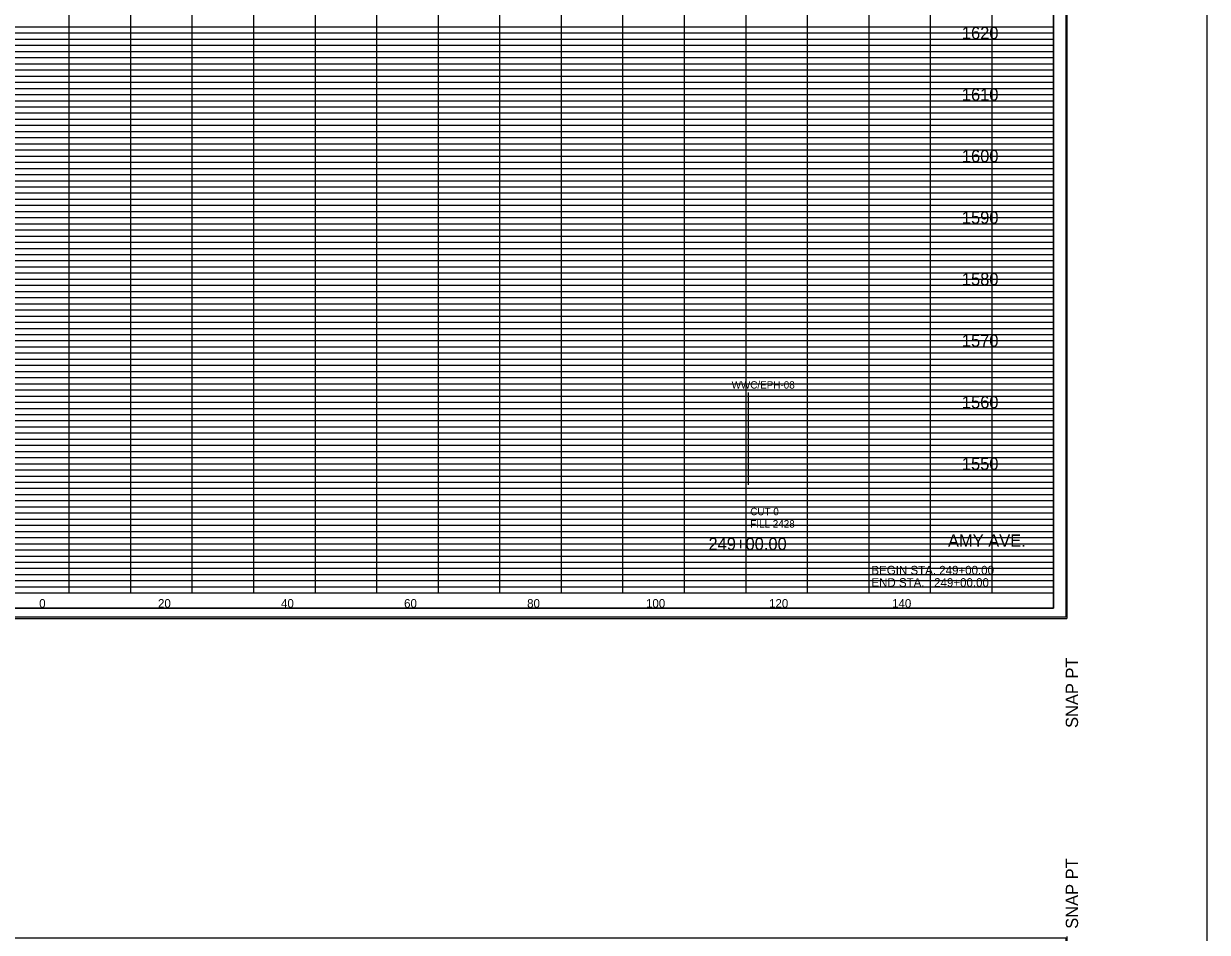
# Model space of a CAD drawing. Extents: x 955 to 1375, y 1248 to 3657.
# Drawn here: x 1152.6 to 1345, y 3104.8 to 3252.5 of the extents above; entities that cross this region are included whole.
import ezdxf

# ---------------------------------------------------------------- set-up
doc = ezdxf.new("R2010")
doc.units = 0
for name, color, linetype in [('DESIGN - SHEET - Corner Text', 7, 'Continuous'), ('DESIGN - SHEET - Light Grid', 7, 'Continuous'), ('DESIGN - SHEET - Linework', 7, 'Continuous'), ('DESIGN - SHEET - Plot Shape', 7, 'Continuous'), ('DESIGN - TYPICAL - Text', 7, 'Continuous'), ('DESIGN - UTILITIES - Cable (Overhead) with Text', 7, 'Continuous'), ('SURVEY - NON-TRANSPORTATION - Features', 7, 'Continuous'), ('SURVEY - NON-TRANSPORTATION - Features Text', 7, 'Continuous')]:
    doc.layers.add(name, color=color, linetype=linetype)

# ---------------------------------------------------------------- blocks, each defined once
blk = doc.blocks.new('XSTSHT')
at = {"layer": 'DESIGN - SHEET - Light Grid'}
for p, q in [((8, 9.2), (16, 9.2)), ((8, 9.1), (16, 9.1)), ((16, 9.2), (24, 9.2)), ((16, 9.1), (24, 9.1)), ((24, 9.2), (32, 9.2)), ((24, 9.1), (32, 9.1)), ((8, 8.9), (16, 8.9)), ((16, 8.9), (24, 8.9)), ((24, 8.9), (32, 8.9)), ((8, 8.8), (16, 8.8)), ((8, 8.7), (16, 8.7)), ((16, 8.8), (24, 8.8)), ((16, 8.7), (24, 8.7)), ((24, 8.8), (32, 8.8)), ((24, 8.7), (32, 8.7)), ((8, 8.6), (16, 8.6)), ((8, 8.5), (16, 8.5)), ((16, 8.6), (24, 8.6)), ((16, 8.5), (24, 8.5)), ((24, 8.6), (32, 8.6)), ((24, 8.5), (32, 8.5)), ((8, 8.4), (16, 8.4)), ((8, 8.3), (16, 8.3)), ((16, 8.4), (24, 8.4)), ((16, 8.3), (24, 8.3)), ((24, 8.4), (32, 8.4)), ((24, 8.3), (32, 8.3)), ((8, 8.2), (16, 8.2)), ((8, 8.1), (16, 8.1)), ((16, 8.2), (24, 8.2)), ((16, 8.1), (24, 8.1)), ((24, 8.2), (32, 8.2)), ((24, 8.1), (32, 8.1)), ((8, 7.9), (16, 7.9)), ((16, 7.9), (24, 7.9)), ((24, 7.9), (32, 7.9)), ((8, 7.8), (16, 7.8)), ((8, 7.7), (16, 7.7)), ((16, 7.8), (24, 7.8)), ((16, 7.7), (24, 7.7)), ((24, 7.8), (32, 7.8)), ((24, 7.7), (32, 7.7)), ((8, 7.6), (16, 7.6)), ((16, 7.6), (24, 7.6)), ((24, 7.6), (32, 7.6)), ((8, 7.5), (16, 7.5)), ((8, 7.4), (16, 7.4)), ((16, 7.5), (24, 7.5)), ((16, 7.4), (24, 7.4)), ((24, 7.5), (32, 7.5)), ((24, 7.4), (32, 7.4)), ((8, 7.3), (16, 7.3)), ((8, 7.2), (16, 7.2)), ((16, 7.3), (24, 7.3)), ((16, 7.2), (24, 7.2)), ((24, 7.3), (32, 7.3)), ((24, 7.2), (32, 7.2)), ((8, 7.1), (16, 7.1)), ((16, 7.1), (24, 7.1)), ((24, 7.1), (32, 7.1)), ((8, 6.9), (16, 6.9)), ((8, 6.8), (16, 6.8)), ((16, 6.9), (24, 6.9)), ((16, 6.8), (24, 6.8)), ((24, 6.9), (32, 6.9)), ((24, 6.8), (32, 6.8)), ((8, 6.7), (16, 6.7)), ((8, 6.6), (16, 6.6)), ((16, 6.7), (24, 6.7)), ((16, 6.6), (24, 6.6)), ((24, 6.7), (32, 6.7)), ((24, 6.6), (32, 6.6)), ((8, 6.5), (16, 6.5)), ((8, 6.4), (16, 6.4)), ((16, 6.5), (24, 6.5)), ((16, 6.4), (24, 6.4)), ((24, 6.5), (32, 6.5)), ((24, 6.4), (32, 6.4)), ((8, 6.3), (16, 6.3)), ((8, 6.2), (16, 6.2)), ((16, 6.3), (24, 6.3)), ((16, 6.2), (24, 6.2)), ((24, 6.3), (32, 6.3)), ((24, 6.2), (32, 6.2)), ((8, 6.1), (16, 6.1)), ((16, 6.1), (24, 6.1)), ((24, 6.1), (32, 6.1)), ((8, 5.9), (16, 5.9)), ((8, 5.8), (16, 5.8)), ((16, 5.9), (24, 5.9)), ((16, 5.8), (24, 5.8)), ((24, 5.9), (32, 5.9)), ((24, 5.8), (32, 5.8)), ((8, 5.7), (16, 5.7)), ((8, 5.6), (16, 5.6)), ((16, 5.7), (24, 5.7)), ((16, 5.6), (24, 5.6)), ((24, 5.7), (32, 5.7)), ((24, 5.6), (32, 5.6)), ((8, 5.5), (16, 5.5)), ((8, 5.4), (16, 5.4)), ((16, 5.5), (24, 5.5)), ((16, 5.4), (24, 5.4)), ((24, 5.5), (32, 5.5)), ((24, 5.4), (32, 5.4)), ((8, 5.3), (16, 5.3)), ((8, 5.2), (16, 5.2)), ((16, 5.3), (24, 5.3)), ((16, 5.2), (24, 5.2)), ((24, 5.3), (32, 5.3)), ((24, 5.2), (32, 5.2)), ((8, 5.1), (16, 5.1)), ((16, 5.1), (24, 5.1)), ((24, 5.1), (32, 5.1)), ((8, 4.9), (16, 4.9)), ((16, 4.9), (24, 4.9)), ((24, 4.9), (32, 4.9)), ((8, 4.8), (16, 4.8)), ((8, 4.7), (16, 4.7)), ((16, 4.8), (24, 4.8)), ((16, 4.7), (24, 4.7)), ((24, 4.8), (32, 4.8)), ((24, 4.7), (32, 4.7)), ((8, 4.6), (16, 4.6)), ((8, 4.5), (16, 4.5)), ((16, 4.6), (24, 4.6)), ((16, 4.5), (24, 4.5)), ((24, 4.6), (32, 4.6)), ((24, 4.5), (32, 4.5)), ((8, 4.4), (16, 4.4)), ((8, 4.3), (16, 4.3)), ((16, 4.4), (24, 4.4)), ((16, 4.3), (24, 4.3)), ((24, 4.4), (32, 4.4)), ((24, 4.3), (32, 4.3)), ((8, 4.2), (16, 4.2)), ((8, 4.1), (16, 4.1)), ((16, 4.2), (24, 4.2)), ((16, 4.1), (24, 4.1)), ((24, 4.2), (32, 4.2)), ((24, 4.1), (32, 4.1)), ((8, 3.9), (16, 3.9)), ((16, 3.9), (24, 3.9)), ((24, 3.9), (32, 3.9)), ((8, 3.8), (16, 3.8)), ((8, 3.7), (16, 3.7)), ((16, 3.8), (24, 3.8)), ((16, 3.7), (24, 3.7)), ((24, 3.8), (32, 3.8)), ((24, 3.7), (32, 3.7)), ((8, 3.6), (16, 3.6)), ((8, 3.5), (16, 3.5)), ((16, 3.6), (24, 3.6)), ((16, 3.5), (24, 3.5)), ((24, 3.6), (32, 3.6)), ((24, 3.5), (32, 3.5)), ((8, 3.4), (16, 3.4)), ((8, 3.3), (16, 3.3)), ((16, 3.4), (24, 3.4)), ((16, 3.3), (24, 3.3)), ((24, 3.4), (32, 3.4)), ((24, 3.3), (32, 3.3)), ((8, 3.2), (16, 3.2)), ((8, 3.1), (16, 3.1)), ((16, 3.2), (24, 3.2)), ((16, 3.1), (24, 3.1)), ((24, 3.2), (32, 3.2)), ((24, 3.1), (32, 3.1)), ((8, 2.9), (16, 2.9)), ((16, 2.9), (24, 2.9)), ((24, 2.9), (32, 2.9)), ((8, 2.8), (16, 2.8)), ((8, 2.7), (16, 2.7)), ((16, 2.8), (24, 2.8)), ((16, 2.7), (24, 2.7)), ((24, 2.8), (32, 2.8)), ((24, 2.7), (32, 2.7)), ((8, 2.6), (16, 2.6)), ((16, 2.6), (24, 2.6)), ((24, 2.6), (32, 2.6)), ((8, 2.5), (16, 2.5)), ((8, 2.4), (16, 2.4)), ((16, 2.5), (24, 2.5)), ((16, 2.4), (24, 2.4)), ((24, 2.5), (32, 2.5)), ((24, 2.4), (32, 2.4)), ((8, 2.3), (16, 2.3)), ((8, 2.2), (16, 2.2)), ((16, 2.3), (24, 2.3)), ((16, 2.2), (24, 2.2)), ((24, 2.3), (32, 2.3)), ((24, 2.2), (32, 2.2)), ((8, 2.1), (16, 2.1)), ((16, 2.1), (24, 2.1)), ((24, 2.1), (32, 2.1)), ((8, 1.9), (16, 1.9)), ((8, 1.8), (16, 1.8)), ((16, 1.9), (24, 1.9)), ((16, 1.8), (24, 1.8)), ((24, 1.9), (32, 1.9)), ((24, 1.8), (32, 1.8)), ((8, 1.7), (16, 1.7)), ((8, 1.6), (16, 1.6)), ((16, 1.7), (24, 1.7)), ((16, 1.6), (24, 1.6)), ((24, 1.7), (32, 1.7)), ((24, 1.6), (32, 1.6)), ((8, 1.5), (16, 1.5)), ((8, 1.4), (16, 1.4)), ((16, 1.5), (24, 1.5)), ((16, 1.4), (24, 1.4)), ((24, 1.5), (32, 1.5)), ((24, 1.4), (32, 1.4)), ((8, 1.3), (16, 1.3)), ((8, 1.2), (16, 1.2)), ((16, 1.3), (24, 1.3)), ((16, 1.2), (24, 1.2)), ((24, 1.3), (32, 1.3)), ((24, 1.2), (32, 1.2)), ((8, 1.1), (16, 1.1)), ((16, 1.1), (24, 1.1)), ((24, 1.1), (32, 1.1)), ((8, 0.9), (16, 0.9)), ((8, 0.8), (16, 0.8)), ((16, 0.9), (24, 0.9)), ((16, 0.8), (24, 0.8)), ((24, 0.9), (32, 0.9)), ((24, 0.8), (32, 0.8)), ((8, 0.7), (16, 0.7)), ((8, 0.6), (16, 0.6)), ((16, 0.7), (24, 0.7)), ((16, 0.6), (24, 0.6)), ((24, 0.7), (32, 0.7)), ((24, 0.6), (32, 0.6)), ((8, 0.5), (16, 0.5)), ((8, 0.4), (16, 0.4)), ((16, 0.5), (24, 0.5)), ((16, 0.4), (24, 0.4)), ((24, 0.5), (32, 0.5)), ((24, 0.4), (32, 0.4)), ((8, 0.3), (16, 0.3)), ((8, 0.2), (16, 0.2)), ((16, 0.3), (24, 0.3)), ((16, 0.2), (24, 0.2)), ((24, 0.3), (32, 0.3)), ((24, 0.2), (32, 0.2)), ((8, 0.1), (16, 0.1)), ((16, 0.1), (24, 0.1)), ((24, 0.1), (32, 0.1))]:
    blk.add_line(p, q, dxfattribs=at)
at = {"layer": 'DESIGN - SHEET - Linework'}
for p, q in [((32.217, 21.414), (32.217, -0.414)), ((16, 0), (16, 21)), ((17, 0), (17, 21)), ((18, 0), (18, 21)), ((19, 0), (19, 21)), ((20, 0), (20, 21)), ((21, 0), (21, 21)), ((22, 0), (22, 21)), ((23, 0), (23, 21)), ((24, 0), (24, 21)), ((25, 0), (25, 21)), ((26, 0), (26, 21)), ((27, 0), (27, 21)), ((28, 0), (28, 20)), ((29, 0), (29, 20)), ((30, 0), (30, 20)), ((31, 0), (31, 20)), ((0, 9), (32, 9)), ((0, 8), (32, 8)), ((0, 7), (32, 7)), ((0, 6), (32, 6)), ((0, 5), (32, 5)), ((0, 4), (32, 4)), ((0, 3), (32, 3)), ((0, 2), (32, 2)), ((0, 1), (32, 1)), ((-1.823, -0.414), (32.217, -0.414))]:
    blk.add_line(p, q, dxfattribs=at)
blk.add_lwpolyline([(0, 21), (0, 0), (32, 0), (32, 21), (0, 21)], dxfattribs=at)
at = {"layer": 'DESIGN - SHEET - Plot Shape'}
for points in [[(-1.803, 21.394), (32.197, 21.394), (32.197, -0.394), (-1.803, -0.394)], [(-0.85, 21), (32, 21), (32, -0.25), (-0.85, -0.25)]]:
    blk.add_lwpolyline(points, close=True, dxfattribs=at)
at = {"layer": 'DESIGN - SHEET - Corner Text'}
for s, p in [('  SNAP PT', (32.397, 21.394)), ('SNAP PT  ', (32.397, -2.194))]:
    blk.add_text(s, height=0.2, rotation=90, dxfattribs=at).set_placement(p)

msp = doc.modelspace()

# ---------------------------------------------------------------- linework, layer by layer
at = {"layer": 'DESIGN - SHEET - Plot Shape'}
msp.add_lwpolyline([(991.5, 3157.5), (1320, 3157.5), (1320, 3370), (991.5, 3370)], close=True, dxfattribs=at)
at = {"layer": 'SURVEY - NON-TRANSPORTATION - Features'}
msp.add_line((1270.4, 3177.55), (1270.4, 3192.55), dxfattribs=at)
at = {"layer": 'SURVEY - NON-TRANSPORTATION - Features Text'}
msp.add_lwpolyline([(955.41, 1505.76), (1344.98, 1505.76), (1344.98, 3398.01), (955.41, 3398.01)], close=True, dxfattribs=at)

# ---------------------------------------------------------------- block references
at = {"layer": 'DESIGN - UTILITIES - Cable (Overhead) with Text', "xscale": 10, "yscale": 10}
for p in [(1000, 3160), (1000, 2890)]:
    msp.add_blockref('XSTSHT', p, dxfattribs=at)

# ---------------------------------------------------------------- texts
at = {"layer": 'DESIGN - SHEET - Corner Text'}
for s, height, p in [('AMY AVE.', 2, (1302.83, 3167.5)), ('BEGIN STA. 249+00.00', 1.4, (1290.38, 3163)), ('END STA.   249+00.00', 1.4, (1290.38, 3161))]:
    msp.add_text(s, height=height, dxfattribs=at).set_placement(p)
at = {"layer": 'DESIGN - TYPICAL - Text'}
for s, height, p in [('     1620     ', 2, (1301.37, 3250)), ('     1610     ', 2, (1301.37, 3240)), ('     1600     ', 2, (1301.37, 3230)), ('     1590     ', 2, (1301.37, 3220)), ('     1580     ', 2, (1301.37, 3210)), ('     1570     ', 2, (1301.37, 3200)), ('     1560     ', 2, (1301.37, 3190)), ('     1550     ', 2, (1301.37, 3180)), ('CUT 0', 1.2, (1270.69, 3172.63)), ('FILL 2428', 1.2, (1270.69, 3170.63)), ('     249+00.00     ', 2, (1260.18, 3166.97)), ('     0     ', 1.4, (1152.51, 3157.6)), ('     0     ', 1.4, (1152.51, 3157.6)), ('     20     ', 1.4, (1171.82, 3157.6)), ('     40     ', 1.4, (1191.82, 3157.6)), ('     60     ', 1.4, (1211.82, 3157.6)), ('     80     ', 1.4, (1231.82, 3157.6)), ('     100     ', 1.4, (1251.14, 3157.6)), ('     120     ', 1.4, (1271.14, 3157.6)), ('     140     ', 1.4, (1291.14, 3157.6))]:
    msp.add_text(s, height=height, dxfattribs=at).set_placement(p)
at = {"layer": 'SURVEY - NON-TRANSPORTATION - Features'}
msp.add_text('WWC/EPH-08', height=1.2, dxfattribs=at).set_placement((1267.66, 3193.21))

doc.saveas('drawing.dxf')
